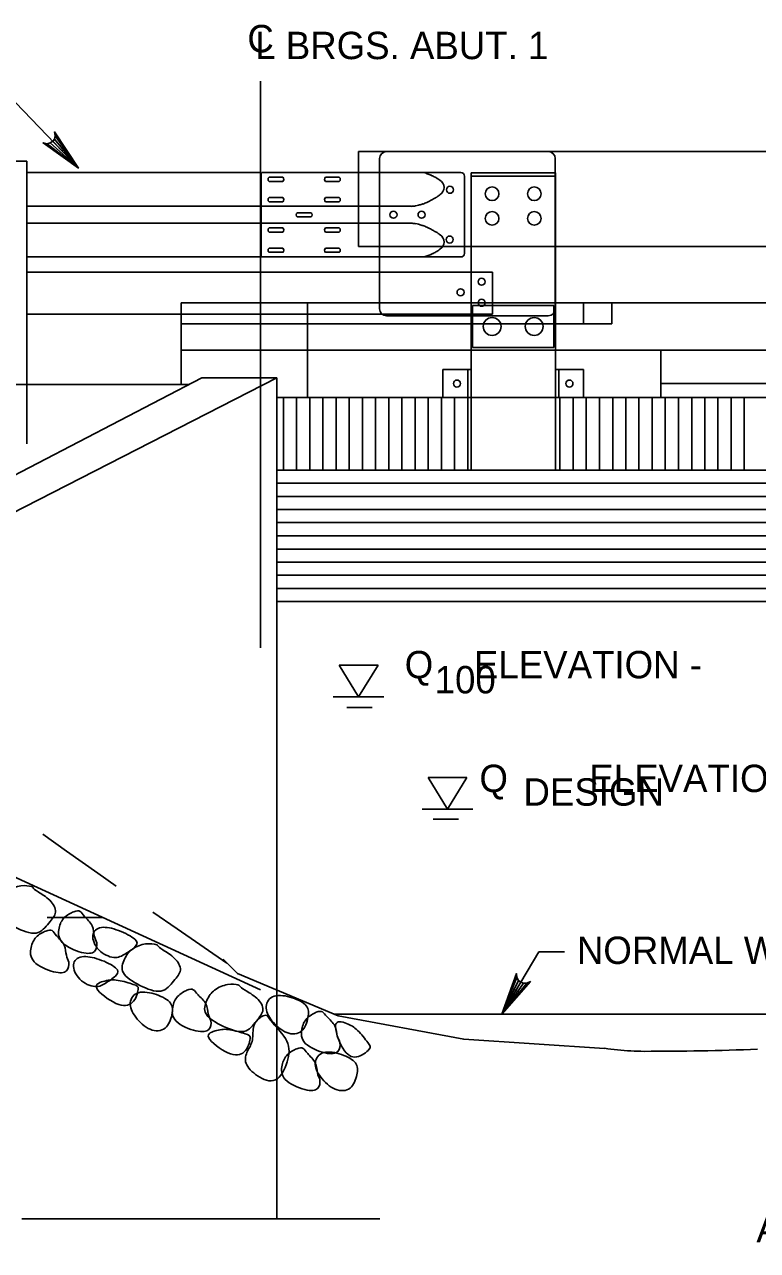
# Model space of a CAD drawing. Extents: x 638263 to 640391, y 293683 to 298655.
# Drawn here: x 638554.8 to 638635.1, y 297942 to 298076.3 of the extents above; entities that cross this region are included whole.
import ezdxf

# ---------------------------------------------------------------- set-up
doc = ezdxf.new("R2010")
doc.units = 0
for name, color, linetype in [('2', 7, 'Continuous'), ('3', 7, 'Continuous'), ('4', 7, 'Continuous'), ('5', 7, 'Continuous'), ('8', 7, 'Continuous'), ('Level 25', 7, 'Continuous')]:
    doc.layers.add(name, color=color, linetype=linetype)

msp = doc.modelspace()

# ---------------------------------------------------------------- linework, layer by layer
at = {"layer": '2'}
for p, q in [((638591.38, 298062.37), (638591.38, 298060.06)), ((638591.38, 298062.37), (638764.38, 298062.37)), ((638555.04, 298060.07), (638580.72, 298060.07)), ((638580.72, 298060.07), (638580.72, 298050.83)), ((638580.79, 298060.07), (638591.38, 298060.07)), ((638581.59, 298059.56), (638583.07, 298059.56)), ((638587.77, 298059.56), (638589.24, 298059.56)), ((638591.38, 298060.07), (638602.59, 298060.07)), ((638591.38, 298060.06), (638591.38, 298051.98)), ((638602.96, 298059.7), (638602.96, 298051.2)), ((638603.69, 298060.06), (638612.93, 298060.06)), ((638603.69, 298045.81), (638603.69, 298060.06)), ((638603.69, 298059.68), (638612.93, 298059.68)), ((638612.93, 298051.98), (638612.93, 298060.06)), ((638581.59, 298059.1), (638583.07, 298059.1)), ((638587.77, 298059.1), (638589.24, 298059.1)), ((638581.59, 298057.35), (638583.07, 298057.35)), ((638581.59, 298056.88), (638583.07, 298056.88)), ((638587.77, 298057.35), (638589.24, 298057.35)), ((638587.77, 298056.88), (638589.24, 298056.88)), ((638555.04, 298056.38), (638591.38, 298056.38)), ((638584.67, 298055.68), (638586.15, 298055.68)), ((638584.67, 298055.22), (638586.15, 298055.22)), ((638591.38, 298056.38), (638597.12, 298056.38)), ((638555.04, 298054.53), (638591.38, 298054.53)), ((638581.59, 298054.02), (638583.07, 298054.02)), ((638587.77, 298054.02), (638589.24, 298054.02)), ((638591.38, 298054.53), (638597.12, 298054.53)), ((638581.59, 298053.56), (638583.07, 298053.56)), ((638587.77, 298053.56), (638589.24, 298053.56)), ((638581.59, 298051.8), (638583.07, 298051.8)), ((638581.59, 298051.34), (638583.07, 298051.34)), ((638587.77, 298051.8), (638589.24, 298051.8)), ((638587.77, 298051.34), (638589.24, 298051.34)), ((638591.38, 298051.98), (638593.69, 298051.98)), ((638593.69, 298051.98), (638603.69, 298051.98)), ((638603.69, 298051.98), (638612.93, 298051.98)), ((638612.93, 298051.98), (638612.93, 298045.81)), ((638612.93, 298051.98), (638651.35, 298051.98)), ((638555.04, 298050.83), (638593.68, 298050.83)), ((638593.68, 298050.83), (638602.59, 298050.83)), ((638555.04, 298049.17), (638593.68, 298049.17)), ((638593.68, 298049.17), (638606.04, 298049.17)), ((638606.04, 298044.55), (638606.04, 298049.17)), ((638555.04, 298044.55), (638571.95, 298044.55)), ((638571.95, 298045.81), (638603.69, 298045.81)), ((638571.95, 298045.81), (638571.95, 298036.87)), ((638571.95, 298044.55), (638606.04, 298044.55)), ((638585.79, 298045.81), (638585.79, 298035.43)), ((638593.68, 298045.81), (638593.68, 298045.15)), ((638603.69, 298045.81), (638603.69, 298027.49)), ((638603.69, 298045.81), (638612.93, 298045.81)), ((638603.85, 298045.53), (638603.85, 298040.92)), ((638603.85, 298045.53), (638612.74, 298045.53)), ((638612.74, 298045.53), (638612.74, 298040.92)), ((638612.93, 298045.81), (638612.93, 298027.49)), ((638612.93, 298045.81), (638651.35, 298045.81)), ((638616.01, 298043.51), (638616.01, 298045.81)), ((638619.1, 298043.51), (638619.1, 298045.81)), ((638571.95, 298043.51), (638619.1, 298043.51)), ((638571.95, 298040.62), (638603.69, 298040.62)), ((638603.69, 298040.62), (638612.93, 298040.62)), ((638603.85, 298040.92), (638612.74, 298040.92)), ((638612.93, 298040.62), (638629.08, 298040.62)), ((638624.46, 298040.62), (638624.46, 298035.43)), ((638624.68, 298040.62), (638651.35, 298040.62)), ((638600.6, 298038.52), (638603.69, 298038.52)), ((638600.6, 298038.52), (638600.6, 298035.43)), ((638603.33, 298038.52), (638603.33, 298035.43)), ((638603.69, 298038.52), (638603.69, 298035.43)), ((638616.02, 298038.52), (638612.93, 298038.52)), ((638612.93, 298038.52), (638612.93, 298035.43)), ((638613.29, 298038.52), (638613.29, 298035.43)), ((638616.02, 298038.52), (638616.02, 298035.43)), ((638624.46, 298036.96), (638638.54, 298036.96)), ((638600.6, 298035.43), (638603.69, 298035.43)), ((638603.69, 298035.43), (638612.93, 298035.43)), ((638616.02, 298035.43), (638612.93, 298035.43)), ((638612.93, 298035.43), (638651.35, 298035.43))]:
    msp.add_line(p, q, dxfattribs=at)
for centre, radius in [((638601.38, 298058.19), 0.385), ((638606, 298057.75), 0.748), ((638610.62, 298057.75), 0.748), ((638595.2, 298055.46), 0.385), ((638598.27, 298055.46), 0.385), ((638606, 298055.06), 0.748), ((638610.62, 298055.06), 0.748), ((638601.35, 298052.74), 0.385), ((638604.85, 298048.12), 0.385), ((638602.54, 298046.96), 0.385), ((638604.85, 298045.81), 0.385), ((638606, 298043.22), 0.978), ((638610.61, 298043.22), 0.978), ((638602.15, 298036.97), 0.385), ((638614.47, 298036.97), 0.385)]:
    msp.add_circle(centre, radius, dxfattribs=at)
for centre, radius, start, end in [((638581.73, 298059.33), 0.269, 120.8559, 239.1441), ((638582.93, 298059.33), 0.269, 300.8559, 59.1441), ((638587.9, 298059.33), 0.269, 120.8559, 239.1441), ((638589.11, 298059.33), 0.269, 300.8559, 59.1441), ((638595.55, 298050.35), 10.17, 71.5066, 72.9766), ((638598.18, 298058.2), 1.88, 68.0907, 71.5066), ((638574.73, 297999.9), 64.73, 67.6851, 68.0907), ((638597.05, 298054.29), 5.93, 66.3453, 67.6851), ((638598.46, 298057.51), 2.42, 63.4251, 66.3453), ((638585.32, 298031.23), 31.8, 62.6202, 63.4251), ((638599.5, 298058.62), 0.955, 54.6771, 62.6202), ((638597.5, 298055.8), 4.42, 50.9849, 54.6771), ((638602.59, 298059.7), 0.369, 0, 90), ((638599.82, 298058.44), 0.916, 301.3851, 59.6468), ((638581.73, 298057.12), 0.269, 120.8559, 239.1441), ((638582.93, 298057.12), 0.269, 300.8559, 59.1441), ((638587.9, 298057.12), 0.269, 120.8559, 239.1441), ((638589.11, 298057.12), 0.269, 300.8559, 59.1441), ((638570.89, 298144.39), 91.96, 287.1115, 287.3611), ((638597.39, 298059.62), 3.14, 287.3611, 288.7111), ((638592.57, 298073.85), 18.18, 288.7111, 290.2329), ((638598.63, 298057.4), 0.644, 290.2329, 298.3215), ((638588.76, 298075.72), 21.45, 298.3215, 298.7501), ((638654.43, 297956.02), 115.08, 118.565, 118.7501), ((638659.82, 297946.11), 126.36, 118.4725, 118.565), ((638412.3, 298402.51), 392.83, 298.4725, 298.525), ((638599.38, 298058.32), 1.09, 298.525, 306.8818), ((638597.07, 298061.4), 4.94, 306.8818, 310.7993), ((638584.81, 298055.45), 0.269, 120.8559, 239.1441), ((638586.01, 298055.45), 0.269, 300.8559, 59.1441), ((638596.89, 298061.4), 5.03, 272.6429, 278.367), ((638597.31, 298058.56), 2.16, 278.367, 287.1115), ((638581.73, 298053.79), 0.269, 120.8559, 239.1441), ((638582.93, 298053.79), 0.269, 300.8559, 59.1441), ((638587.9, 298053.79), 0.269, 120.8559, 239.1441), ((638589.11, 298053.79), 0.269, 300.8559, 59.1441), ((638596.89, 298049.5), 5.03, 81.633, 87.3571), ((638597.31, 298052.35), 2.16, 72.8885, 81.633), ((638570.89, 297966.52), 91.96, 72.6389, 72.8885), ((638597.39, 298051.29), 3.14, 71.2889, 72.6389), ((638592.57, 298037.05), 18.18, 69.7671, 71.2889), ((638598.63, 298053.5), 0.644, 61.6785, 69.7671), ((638588.76, 298035.18), 21.45, 61.2499, 61.6785), ((638654.43, 298154.89), 115.08, 241.2499, 241.435), ((638659.82, 298164.79), 126.36, 241.435, 241.5275), ((638412.3, 297708.4), 392.83, 61.475, 61.5275), ((638599.38, 298052.59), 1.09, 53.1182, 61.475), ((638597.07, 298049.51), 4.94, 49.2007, 53.1182), ((638599.82, 298052.47), 0.916, 300.3532, 58.6149), ((638581.73, 298051.57), 0.269, 120.8559, 239.1441), ((638582.93, 298051.57), 0.269, 300.8559, 59.1441), ((638587.9, 298051.57), 0.269, 120.8559, 239.1441), ((638589.11, 298051.57), 0.269, 300.8559, 59.1441), ((638598.46, 298053.39), 2.42, 293.6547, 296.5749), ((638585.32, 298079.67), 31.8, 296.5749, 297.3798), ((638599.5, 298052.28), 0.955, 297.3798, 305.3229), ((638597.5, 298055.11), 4.42, 305.3229, 309.0151), ((638602.59, 298051.2), 0.369, 270, 0), ((638595.55, 298060.56), 10.17, 287.0234, 288.4934), ((638598.18, 298052.7), 1.88, 288.4934, 291.9093), ((638574.73, 298111), 64.73, 291.9093, 292.3149), ((638597.05, 298056.61), 5.93, 292.3149, 293.6547)]:
    msp.add_arc(centre, radius, start, end, dxfattribs=at)
at = {"layer": '3'}
for p, q in [((638555.04, 298061.34), (638550.72, 298061.34)), ((638555.04, 298036.87), (638555.04, 298061.34)), ((638572.83, 298036.87), (638507.64, 298036.87)), ((638574.22, 298037.59), (638509.09, 298003.71)), ((638582.43, 298037.59), (638516.23, 298003.71)), ((638555.04, 298036.87), (638555.04, 298030.38)), ((638582.43, 298037.59), (638574.22, 298037.59)), ((638582.43, 298033.26), (638582.43, 298037.59)), ((638582.43, 298035.43), (638603.69, 298035.43)), ((638582.43, 298033.26), (638582.43, 297970.54)), ((638582.43, 298027.49), (638761.22, 298027.49)), ((638582.43, 298013.08), (638761.22, 298013.08)), ((638539.25, 297989.54), (638580.63, 297970.56)), ((638557.28, 297978.48), (638563.38, 297978.48)), ((638582.43, 297970.54), (638582.43, 297945.49)), ((638588.79, 297967.88), (638749.52, 297967.88)), ((638554.5, 297945.49), (638593.69, 297945.49))]:
    msp.add_line(p, q, dxfattribs=at)
for centre, radius, start, end in [((638627.57, 298034.65), 71.1, 262.5202, 263.6598), ((638622.62, 297990.13), 26.31, 263.6598, 270.0618), ((638622.25, 298334.72), 370.9, 270.0618, 271.9788)]:
    msp.add_arc(centre, radius, start, end, dxfattribs=at)
for points in [[(638555.73, 297981.73), (638555.78, 297981.65), (638556.11, 297981.36), (638557.7, 297980.45), (638558.49, 297979.01), (638557.49, 297977.96), (638556.29, 297976.34), (638553.71, 297977.34), (638551.49, 297978.75), (638552.04, 297980.35), (638552.83, 297981.47), (638554.43, 297982.08), (638555.78, 297981.87), (638555.67, 297981.82), (638555.73, 297981.73)], [(638562.44, 297976.48), (638562.51, 297976.18), (638562.81, 297975.81), (638562.66, 297974.59), (638561.31, 297974.42), (638558.42, 297975.67), (638558.51, 297977.43), (638559.03, 297978.53), (638560.29, 297979.23), (638560.94, 297979.26), (638561.24, 297978.65), (638562.41, 297977.62), (638562.37, 297976.78), (638562.44, 297976.48)], [(638566.93, 297975.29), (638566.69, 297975.03), (638565.82, 297974.48), (638564.71, 297973.84), (638562.73, 297974.78), (638561.97, 297976.7), (638563.06, 297977.61), (638565.08, 297977.17), (638567.26, 297976.03), (638567.17, 297975.55), (638566.93, 297975.29)], [(638559.38, 297974.36), (638559.44, 297974.06), (638559.75, 297973.69), (638559.59, 297972.47), (638558.25, 297972.3), (638555.35, 297973.55), (638555.45, 297975.31), (638555.96, 297976.41), (638557.22, 297977.11), (638557.87, 297977.15), (638558.17, 297976.53), (638559.35, 297975.5), (638559.31, 297974.66), (638559.38, 297974.36)], [(638569.39, 297975.38), (638569.45, 297975.29), (638569.78, 297975.01), (638571.37, 297974.09), (638572.16, 297972.66), (638571.16, 297971.61), (638569.95, 297969.98), (638567.38, 297970.98), (638565.16, 297972.39), (638565.7, 297973.99), (638566.49, 297975.11), (638568.1, 297975.72), (638569.44, 297975.51), (638569.34, 297975.46), (638569.39, 297975.38)], [(638564.84, 297972.17), (638564.61, 297971.91), (638563.76, 297971.33), (638562.67, 297970.66), (638560.66, 297971.55), (638559.85, 297973.46), (638560.92, 297974.39), (638562.95, 297974), (638565.16, 297972.92), (638565.08, 297972.43), (638564.84, 297972.17)], [(638566.7, 297971.16), (638567.13, 297971.03), (638567.43, 297970.93), (638566.78, 297968.86), (638565.06, 297968.64), (638561.88, 297971.02), (638563.71, 297971.6), (638564.9, 297971.73), (638566.28, 297971.29), (638566.7, 297971.16)], [(638574.91, 297967.93), (638574.98, 297967.63), (638575.3, 297967.27), (638575.18, 297966.04), (638573.84, 297965.84), (638570.91, 297967.01), (638570.96, 297968.77), (638571.44, 297969.89), (638572.69, 297970.63), (638573.34, 297970.67), (638573.65, 297970.07), (638574.85, 297969.07), (638574.84, 297968.23), (638574.91, 297967.93)], [(638578.37, 297970.96), (638578.43, 297970.88), (638578.76, 297970.6), (638580.37, 297969.72), (638581.2, 297968.31), (638580.23, 297967.24), (638579.07, 297965.58), (638576.47, 297966.51), (638574.21, 297967.87), (638574.72, 297969.48), (638575.48, 297970.62), (638577.06, 297971.27), (638578.41, 297971.1), (638578.31, 297971.04), (638578.37, 297970.96)], [(638570.78, 297969.11), (638571.05, 297968.74), (638571.02, 297967.9), (638570.39, 297966.08), (638568.55, 297965.94), (638566.8, 297967.56), (638566.1, 297969.2), (638567.07, 297970.53), (638569.34, 297970.13), (638570.5, 297969.48), (638570.78, 297969.11)], [(638585.65, 297968.81), (638585.94, 297968.45), (638585.93, 297967.61), (638585.34, 297965.76), (638583.51, 297965.58), (638581.72, 297967.16), (638580.98, 297968.77), (638581.91, 297970.14), (638584.19, 297969.79), (638585.36, 297969.17), (638585.65, 297968.81)], [(638589.05, 297965.51), (638589.12, 297965.21), (638589.44, 297964.85), (638589.31, 297963.63), (638587.98, 297963.42), (638585.05, 297964.6), (638585.1, 297966.35), (638585.58, 297967.47), (638586.83, 297968.21), (638587.48, 297968.25), (638587.79, 297967.65), (638588.99, 297966.65), (638588.98, 297965.81), (638589.05, 297965.51)], [(638581.36, 297967.73), (638581.5, 297967.64), (638581.62, 297967.19), (638583.94, 297964.94), (638583.75, 297962.72), (638582.42, 297960.1), (638580.2, 297961.05), (638578.74, 297962.52), (638579.18, 297963.91), (638579.9, 297964.94), (638579.71, 297966.78), (638580.78, 297967.71), (638581.22, 297967.82), (638581.36, 297967.73)], [(638592.38, 297964.79), (638592.65, 297964.44), (638592.85, 297964.19), (638591.13, 297962.86), (638589.6, 297963.66), (638588.35, 297967.44), (638590.18, 297966.87), (638591.23, 297966.3), (638592.11, 297965.14), (638592.38, 297964.79)], [(638578.96, 297965.75), (638579.38, 297965.61), (638579.69, 297965.52), (638579.04, 297963.45), (638577.32, 297963.23), (638574.14, 297965.61), (638575.96, 297966.18), (638577.15, 297966.32), (638578.54, 297965.88), (638578.96, 297965.75)], [(638586.87, 297961.46), (638586.93, 297961.16), (638587.24, 297960.8), (638587.08, 297959.57), (638585.74, 297959.4), (638582.85, 297960.65), (638582.94, 297962.41), (638583.45, 297963.51), (638584.71, 297964.22), (638585.37, 297964.25), (638585.66, 297963.64), (638586.84, 297962.6), (638586.8, 297961.76), (638586.87, 297961.46)], [(638591.04, 297962.55), (638591.32, 297962.18), (638591.28, 297961.34), (638590.65, 297959.51), (638588.81, 297959.38), (638587.06, 297961), (638586.37, 297962.63), (638587.34, 297963.97), (638589.61, 297963.56), (638590.76, 297962.92), (638591.04, 297962.55)]]:
    msp.add_open_spline(points, degree=3, dxfattribs=at)
at = {"layer": '4'}
for p, q in [((638580.63, 298070.1), (638580.63, 298008.01)), ((638560.71, 298060.57), (638552.06, 298069.54)), ((638589.26, 298006.13), (638591.38, 298002.64)), ((638589.26, 298006.13), (638593.51, 298006.13)), ((638593.51, 298006.13), (638591.38, 298002.64)), ((638591.38, 298002.64), (638588.61, 298002.64)), ((638591.38, 298002.64), (638594.15, 298002.64)), ((638590.08, 298001.49), (638592.85, 298001.49)), ((638598.98, 297993.83), (638603.23, 297993.83)), ((638598.98, 297993.83), (638601.11, 297990.34)), ((638603.23, 297993.83), (638601.11, 297990.34)), ((638601.11, 297990.34), (638598.34, 297990.34)), ((638601.11, 297990.34), (638603.88, 297990.34)), ((638599.55, 297989.26), (638602.32, 297989.26)), ((638607.08, 297967.88), (638611.1, 297974.73)), ((638611.1, 297974.73), (638613.91, 297974.73))]:
    msp.add_line(p, q, dxfattribs=at)
for points in [[(638560.71, 298060.57), (638556.84, 298063.32), (638557.27, 298063.24), (638557.62, 298063.32), (638557.89, 298063.5), (638558.07, 298063.75), (638558.17, 298064.1), (638558.1, 298064.53), (638560.71, 298060.57), (638558.17, 298064.1), (638558.07, 298063.75), (638560.71, 298060.57), (638557.89, 298063.5), (638557.62, 298063.32), (638560.71, 298060.57), (638557.27, 298063.24)], [(638618.31, 297964.15), (638602.9, 297965.15), (638589.15, 297967.72), (638578.11, 297972.34), (638576.54, 297973.9)], [(638607.08, 297967.88), (638608.68, 297972.34), (638608.72, 297971.9), (638608.89, 297971.59), (638609.14, 297971.38), (638609.43, 297971.27), (638609.8, 297971.27), (638610.19, 297971.46), (638607.08, 297967.88), (638609.8, 297971.27), (638609.43, 297971.27), (638607.08, 297967.88), (638609.14, 297971.38), (638608.89, 297971.59), (638607.08, 297967.88), (638608.72, 297971.9)]]:
    msp.add_lwpolyline(points, dxfattribs=at)
msp.add_lwpolyline([(638608.19, 297970.72), (638609.02, 297970.23), (638607.14, 297967.99)], close=True, dxfattribs=at)
at = {"layer": '5'}
for p, q in [((638583.15, 298035.43), (638583.15, 298027.49)), ((638584.59, 298035.43), (638584.59, 298027.49)), ((638586.04, 298035.43), (638586.04, 298027.49)), ((638587.48, 298035.43), (638587.48, 298027.49)), ((638588.92, 298035.43), (638588.92, 298027.49)), ((638590.36, 298035.43), (638590.36, 298027.49)), ((638591.8, 298035.43), (638591.8, 298027.49)), ((638593.24, 298035.43), (638593.24, 298027.49)), ((638594.69, 298035.43), (638594.69, 298027.49)), ((638596.13, 298035.43), (638596.13, 298027.49)), ((638597.57, 298035.43), (638597.57, 298027.49)), ((638599.01, 298035.43), (638599.01, 298027.49)), ((638600.45, 298035.43), (638600.45, 298027.49)), ((638601.89, 298035.43), (638601.89, 298027.49)), ((638603.34, 298035.43), (638603.34, 298027.49)), ((638613.43, 298035.43), (638613.43, 298027.49)), ((638614.87, 298035.43), (638614.87, 298027.49)), ((638616.31, 298035.43), (638616.31, 298027.49)), ((638617.75, 298035.43), (638617.75, 298027.49)), ((638619.2, 298035.43), (638619.2, 298027.49)), ((638620.64, 298035.43), (638620.64, 298027.49)), ((638622.08, 298035.43), (638622.08, 298027.49)), ((638623.52, 298035.43), (638623.52, 298027.49)), ((638624.96, 298035.43), (638624.96, 298027.49)), ((638626.41, 298035.43), (638626.41, 298027.49)), ((638627.85, 298035.43), (638627.85, 298027.49)), ((638629.29, 298035.43), (638629.29, 298027.49)), ((638630.73, 298035.43), (638630.73, 298027.49)), ((638632.17, 298035.43), (638632.17, 298027.49)), ((638633.61, 298035.43), (638633.61, 298027.49)), ((638582.43, 298026.05), (638761.22, 298026.05)), ((638582.43, 298024.61), (638761.22, 298024.61)), ((638582.43, 298023.17), (638761.22, 298023.17)), ((638582.43, 298021.73), (638761.22, 298021.73)), ((638582.43, 298020.29), (638761.22, 298020.29)), ((638582.43, 298018.84), (638761.22, 298018.84)), ((638582.43, 298017.4), (638761.22, 298017.4)), ((638582.43, 298015.96), (638761.22, 298015.96)), ((638582.43, 298014.52), (638761.22, 298014.52))]:
    msp.add_line(p, q, dxfattribs=at)
at = {"layer": '8'}
for p, q in [((638559.41, 297985.76), (638556.81, 297987.61)), ((638562.84, 297983.32), (638559.41, 297985.76)), ((638564.83, 297981.91), (638562.84, 297983.32)), ((638571.51, 297977.24), (638568.86, 297979.08)), ((638576.96, 297973.49), (638571.51, 297977.24))]:
    msp.add_line(p, q, dxfattribs=at)
at = {"layer": 'Level 25'}
for p, q in [((638594.45, 298062.37), (638612.15, 298062.37)), ((638593.68, 298061.6), (638593.68, 298060.06)), ((638612.92, 298061.6), (638612.92, 298060.06)), ((638593.68, 298060.06), (638593.68, 298050.83)), ((638612.92, 298060.06), (638612.92, 298045.15)), ((638593.68, 298050.83), (638593.68, 298045.81)), ((638594.45, 298044.38), (638612.15, 298044.38))]:
    msp.add_line(p, q, dxfattribs=at)
for centre, start, end in [((638594.45, 298061.6), 90, 180), ((638612.15, 298061.6), 0, 90), ((638594.45, 298045.15), 180, 270), ((638612.15, 298045.15), 270, 0)]:
    msp.add_arc(centre, 0.77, start, end, dxfattribs=at)

# ---------------------------------------------------------------- texts
at = {"layer": '4'}
for s, p in [('C', (638579.2, 298073.25)), ('L BRGS. ABUT. 1', (638580.06, 298072.5)), ('Q    ELEVATION - ', (638596.43, 298004.68)), ('100', (638599.71, 298003.03)), ('Q        ELEVATION - ', (638604.61, 297992.22)), ('DESIGN', (638609.43, 297990.73)), ('NORMAL WATER ELEV. -', (638615.28, 297973.39)), ('AS PER DESIGN (MIN. R-6)', (638634.94, 297942.91))]:
    msp.add_text(s, height=3, dxfattribs=at).set_placement(p)

doc.saveas('drawing.dxf')
